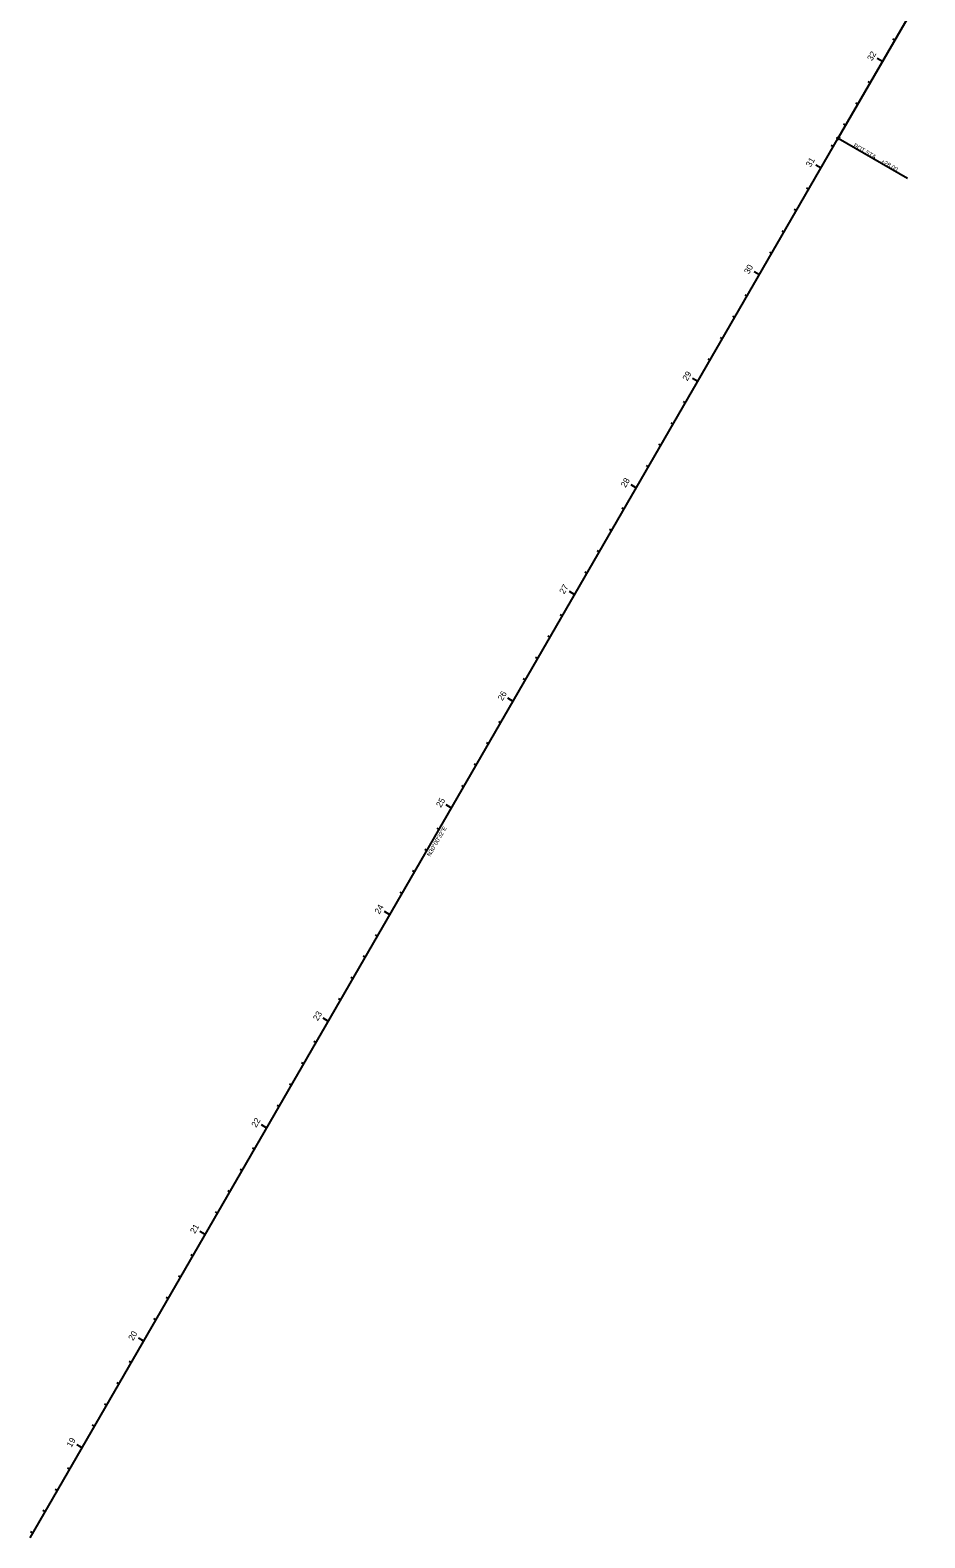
# Model space of a CAD drawing. Extents: x 2005660 to 2007493, y 401364 to 404817.
# Drawn here: x 2006095 to 2006822, y 401364 to 402588 of the extents above; entities that cross this region are included whole.
import ezdxf

# ---------------------------------------------------------------- set-up
doc = ezdxf.new("R2010")
doc.units = 0
for name, color, linetype in [('ConstLines', 7, 'Continuous'), ('CurbBack', 7, 'Continuous'), ('PavtAsphalt', 7, 'Continuous'), ('PavtAsphalt_ep', 7, 'Continuous'), ('PavtMilling', 7, 'Continuous'), ('ScratchEle_dp', 7, 'Continuous'), ('ShldrPaved', 7, 'Continuous'), ('SidewalkFront', 7, 'Continuous'), ('TextAlgnTicks5000', 7, 'Continuous'), ('TrafSeparator', 7, 'Continuous')]:
    doc.layers.add(name, color=color, linetype=linetype)

msp = doc.modelspace()

# ---------------------------------------------------------------- linework, layer by layer
at = {"layer": 'PavtAsphalt'}
for p, q in [((2006797.4, 402580.3), (2006795.7, 402581.3)), ((2006787.4, 402563), (2006783.1, 402565.5)), ((2006777.4, 402545.7), (2006775.7, 402546.7)), ((2006767.4, 402528.3), (2006765.7, 402529.3)), ((2006757.4, 402511), (2006755.7, 402512)), ((2006747.4, 402493.7), (2006745.7, 402494.7)), ((2006737.4, 402476.4), (2006733.1, 402478.9)), ((2006727.4, 402459.1), (2006725.7, 402460.1)), ((2006717.4, 402441.7), (2006715.7, 402442.7)), ((2006707.4, 402424.4), (2006705.7, 402425.4)), ((2006697.4, 402407.1), (2006695.7, 402408.1)), ((2006687.4, 402389.8), (2006683.1, 402392.3)), ((2006677.4, 402372.5), (2006675.7, 402373.5)), ((2006667.4, 402355.2), (2006665.7, 402356.2)), ((2006657.4, 402337.8), (2006655.7, 402338.8)), ((2006647.4, 402320.5), (2006645.7, 402321.5)), ((2006637.4, 402303.2), (2006633.1, 402305.7)), ((2006627.4, 402285.9), (2006625.7, 402286.9)), ((2006617.4, 402268.6), (2006615.7, 402269.6)), ((2006607.4, 402251.2), (2006605.7, 402252.2)), ((2006597.4, 402233.9), (2006595.7, 402234.9)), ((2006587.4, 402216.6), (2006583.1, 402219.1)), ((2006577.4, 402199.3), (2006575.7, 402200.3)), ((2006567.4, 402182), (2006565.7, 402183)), ((2006557.4, 402164.6), (2006555.7, 402165.6)), ((2006547.4, 402147.3), (2006545.7, 402148.3)), ((2006537.4, 402130), (2006533.1, 402132.5)), ((2006527.4, 402112.7), (2006525.6, 402113.7)), ((2006517.4, 402095.4), (2006515.6, 402096.4)), ((2006507.4, 402078.1), (2006505.6, 402079.1)), ((2006497.4, 402060.7), (2006495.6, 402061.7)), ((2006487.4, 402043.4), (2006483, 402045.9)), ((2006477.4, 402026.1), (2006475.6, 402027.1)), ((2006467.4, 402008.8), (2006465.6, 402009.8)), ((2006457.4, 401991.5), (2006455.6, 401992.5)), ((2006447.4, 401974.1), (2006445.6, 401975.1)), ((2006437.4, 401956.8), (2006433, 401959.3)), ((2006427.4, 401939.5), (2006425.6, 401940.5)), ((2006417.3, 401922.2), (2006415.6, 401923.2)), ((2006407.3, 401904.9), (2006405.6, 401905.9)), ((2006397.3, 401887.5), (2006395.6, 401888.5)), ((2006387.3, 401870.2), (2006383, 401872.7)), ((2006377.3, 401852.9), (2006375.6, 401853.9)), ((2006367.3, 401835.6), (2006365.6, 401836.6)), ((2006357.3, 401818.3), (2006355.6, 401819.3)), ((2006347.3, 401800.9), (2006345.6, 401801.9)), ((2006337.3, 401783.6), (2006333, 401786.1)), ((2006327.3, 401766.3), (2006325.6, 401767.3)), ((2006317.3, 401749), (2006315.6, 401750)), ((2006307.3, 401731.7), (2006305.6, 401732.7)), ((2006297.3, 401714.4), (2006295.6, 401715.4)), ((2006287.3, 401697), (2006283, 401699.5)), ((2006277.3, 401679.7), (2006275.6, 401680.7)), ((2006267.3, 401662.4), (2006265.6, 401663.4)), ((2006257.3, 401645.1), (2006255.6, 401646.1)), ((2006247.3, 401627.8), (2006245.6, 401628.8)), ((2006237.3, 401610.4), (2006233, 401612.9)), ((2006227.3, 401593.1), (2006225.6, 401594.1)), ((2006217.3, 401575.8), (2006215.6, 401576.8)), ((2006207.3, 401558.5), (2006205.6, 401559.5)), ((2006197.3, 401541.2), (2006195.6, 401542.2)), ((2006187.3, 401523.8), (2006183, 401526.3)), ((2006177.3, 401506.5), (2006175.6, 401507.5)), ((2006167.3, 401489.2), (2006165.5, 401490.2)), ((2006157.3, 401471.9), (2006155.5, 401472.9)), ((2006147.3, 401454.6), (2006145.5, 401455.6)), ((2006137.3, 401437.2), (2006132.9, 401439.8)), ((2006127.3, 401419.9), (2006125.5, 401420.9)), ((2006117.3, 401402.6), (2006115.5, 401403.6)), ((2006107.3, 401385.3), (2006105.5, 401386.3)), ((2006097.3, 401368), (2006095.5, 401369))]:
    msp.add_line(p, q, dxfattribs=at)
at = {"layer": 'PavtAsphalt_ep'}
for p, q in [((2006751.4, 402500.6), (2007493.3, 403785.1)), ((2006095.1, 401364.2), (2006751.4, 402500.6))]:
    msp.add_line(p, q, dxfattribs=at)
at = {"layer": 'ScratchEle_dp'}
for p, q in [((2006787.4, 402563), (2006785.7, 402564)), ((2006737.4, 402476.4), (2006735.7, 402477.4)), ((2006687.4, 402389.8), (2006683.1, 402392.3)), ((2006637.4, 402303.2), (2006635.7, 402304.2)), ((2006587.4, 402216.6), (2006585.7, 402217.6)), ((2006537.4, 402130), (2006535.6, 402131)), ((2006487.4, 402043.4), (2006485.6, 402044.4)), ((2006437.4, 401956.8), (2006433, 401959.3)), ((2006387.3, 401870.2), (2006385.6, 401871.2)), ((2006337.3, 401783.6), (2006335.6, 401784.6)), ((2006287.3, 401697), (2006285.6, 401698)), ((2006237.3, 401610.4), (2006235.6, 401611.4)), ((2006187.3, 401523.8), (2006183, 401526.3)), ((2006137.3, 401437.2), (2006135.5, 401438.2))]:
    msp.add_line(p, q, dxfattribs=at)
at = {"layer": 'SidewalkFront'}
msp.add_line((2006751.4, 402500.6), (2006807.7, 402468.1), dxfattribs=at)
msp.add_circle((2006751.4, 402500.6), 1, dxfattribs=at)
at = {"layer": 'TextAlgnTicks5000'}
for p, q in [((2006687.4, 402389.8), (2006685.7, 402390.8)), ((2006187.3, 401523.8), (2006185.6, 401524.8))]:
    msp.add_line(p, q, dxfattribs=at)
at = {"layer": 'TrafSeparator'}
for p, q in [((2006787.4, 402563), (2006785.7, 402564)), ((2006687.4, 402389.8), (2006683.1, 402392.3)), ((2006587.4, 402216.6), (2006585.7, 402217.6)), ((2006487.4, 402043.4), (2006485.6, 402044.4)), ((2006387.3, 401870.2), (2006385.6, 401871.2)), ((2006287.3, 401697), (2006285.6, 401698)), ((2006187.3, 401523.8), (2006183, 401526.3))]:
    msp.add_line(p, q, dxfattribs=at)

# ---------------------------------------------------------------- texts
at = {"layer": 'ConstLines'}
for s, p in [('30', (2006678.8, 402389.9)), ('25', (2006428.7, 401956.8)), ('20', (2006178.7, 401523.9))]:
    msp.add_text(s, height=4.98, rotation=59.9911, dxfattribs=at).set_placement(p)
at = {"layer": 'CurbBack'}
for s, p in [('30', (2006678.8, 402389.9)), ('20', (2006178.7, 401523.9))]:
    msp.add_text(s, height=4.98, rotation=59.9911, dxfattribs=at).set_placement(p)
at = {"layer": 'PavtMilling'}
for s, p in [('32', (2006778.8, 402563)), ('31', (2006729, 402476.8)), ('30', (2006678.8, 402389.9)), ('29', (2006628.8, 402303.2)), ('28', (2006578.7, 402216.6)), ('27', (2006528.8, 402130.1)), ('26', (2006478.7, 402043.5)), ('25', (2006428.7, 401956.8)), ('24', (2006378.7, 401870.3)), ('23', (2006328.7, 401783.6)), ('22', (2006278.7, 401697)), ('21', (2006228.9, 401610.8)), ('20', (2006178.7, 401523.9)), ('19', (2006128.6, 401437.3))]:
    msp.add_text(s, height=4.98, rotation=59.9911, dxfattribs=at).set_placement(p)
at = {"layer": 'ShldrPaved'}
msp.add_text('N30°00\'32"E', height=3.48, rotation=59.9911, dxfattribs=at).set_placement((2006420, 401917.1))
at = {"layer": 'SidewalkFront'}
for s, p in [('POT', (2006763.3, 402493.8)), (' STA. ', (2006771.7, 402488.9)), ('+28.00', (2006785.7, 402480.9))]:
    msp.add_text(s, height=3.48, rotation=329.9911, dxfattribs=at).set_placement(p)

doc.saveas('drawing.dxf')
